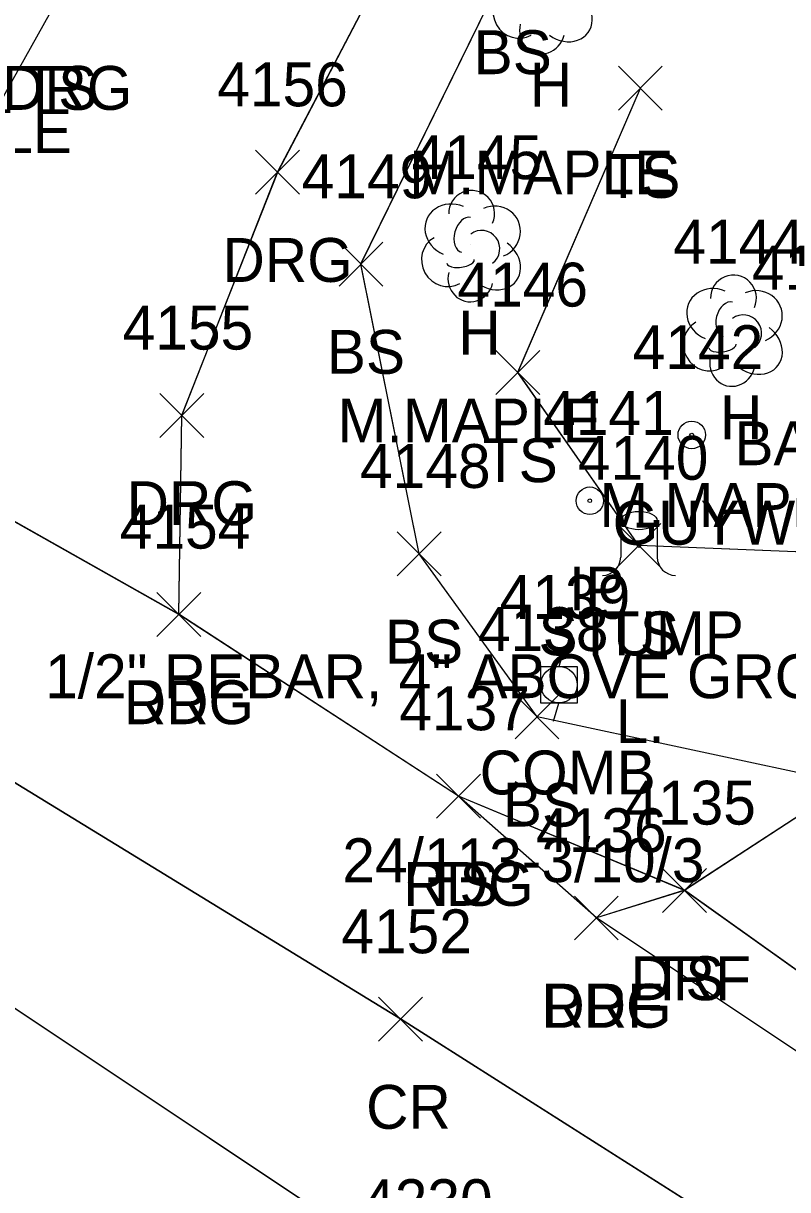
# Model space of a CAD drawing. Extents: x 1554668 to 1563881, y 831386 to 834374.
# Drawn here: x 1562024.3 to 1562059.1, y 834220.5 to 834273.7 of the extents above; entities that cross this region are included whole.
import ezdxf

# ---------------------------------------------------------------- set-up
doc = ezdxf.new("R2010")
doc.units = 0
for name, color, linetype in [('L_A', 7, 'Continuous'), ('L_C', 7, 'Continuous'), ('L_I', 7, 'Continuous'), ('L_TIC', 7, 'Continuous'), ('LELB', 7, 'Continuous'), ('LTD', 7, 'Continuous'), ('LTS', 7, 'Continuous'), ('M_A', 7, 'Continuous'), ('M_C', 7, 'Continuous'), ('M_I', 7, 'Continuous'), ('MPIR', 7, 'Continuous'), ('P_A', 7, 'Continuous'), ('P_I', 7, 'Continuous'), ('P_TIC', 7, 'Continuous'), ('PEU', 7, 'Continuous'), ('PRC', 7, 'Continuous'), ('R_A', 7, 'Continuous'), ('R_I', 7, 'Continuous'), ('R_TIC', 7, 'Continuous'), ('RDF', 7, 'Continuous'), ('RDG', 7, 'Continuous'), ('U_A', 7, 'Continuous'), ('U_C', 7, 'Continuous'), ('U_I', 7, 'Continuous'), ('UP', 7, 'Continuous'), ('UPGW', 7, 'Continuous')]:
    doc.layers.add(name, color=color, linetype=linetype)

msp = doc.modelspace()

# ---------------------------------------------------------------- linework, layer by layer
at = {"layer": 'L_TIC'}
for points in [[(1562051.426, 834269.699), (1562053.426, 834271.699)], [(1562053.426, 834269.699), (1562051.426, 834271.699)], [(1562038.694, 834261.682), (1562040.694, 834263.682)], [(1562040.694, 834261.682), (1562038.694, 834263.682)], [(1562045.838, 834256.746), (1562047.838, 834258.746)], [(1562047.838, 834256.746), (1562045.838, 834258.746)], [(1562051.36, 834248.855), (1562053.36, 834250.855)], [(1562053.36, 834248.855), (1562051.36, 834250.855)], [(1562041.344, 834248.48), (1562043.344, 834250.48)], [(1562043.344, 834248.48), (1562041.344, 834250.48)], [(1562046.718, 834241.051), (1562048.718, 834243.051)], [(1562048.718, 834241.051), (1562046.718, 834243.051)], [(1562043.136, 834237.439), (1562045.136, 834239.439)], [(1562045.136, 834237.439), (1562043.136, 834239.439)], [(1562053.435, 834233.14), (1562055.435, 834235.14)], [(1562055.435, 834233.14), (1562053.435, 834235.14)]]:
    msp.add_lwpolyline(points, dxfattribs=at)
at = {"layer": 'LELB'}
for points in [[(1562274.311, 834171.295), (1562269.484, 834154.313), (1562262.795, 834141.276), (1562258.276, 834136.975), (1562255.128, 834134.812), (1562254.728, 834133.197), (1562248.809, 834134.873), (1562237.208, 834134.057), (1562209.954, 834148.175), (1562185.935, 834159.727), (1562146.304, 834177.205), (1562126.106, 834188.395), (1562101.793, 834201.545), (1562083.048, 834212.879), (1562078.957, 834226.941), (1562061.906, 834239.007), (1562047.718, 834242.051), (1562042.344, 834249.48), (1562039.694, 834262.682), (1562046.385, 834276.336)], [(1562274.319, 834171.3), (1562269.492, 834154.32), (1562262.801, 834141.275), (1562258.282, 834136.979), (1562255.131, 834134.817), (1562254.731, 834133.201), (1562248.817, 834134.876), (1562237.219, 834134.061), (1562209.965, 834148.177), (1562185.942, 834159.73), (1562146.305, 834177.208), (1562126.107, 834188.395), (1562101.796, 834201.554), (1562083.051, 834212.885), (1562078.962, 834226.944), (1562061.908, 834239.014), (1562047.722, 834242.055), (1562042.349, 834249.484), (1562039.695, 834262.69), (1562046.39, 834276.339)], [(1562274.319, 834171.3), (1562269.492, 834154.32), (1562262.801, 834141.275), (1562258.282, 834136.979), (1562255.131, 834134.817), (1562254.731, 834133.201), (1562248.817, 834134.876), (1562237.219, 834134.061), (1562209.965, 834148.177), (1562185.942, 834159.73), (1562146.305, 834177.208), (1562126.107, 834188.395), (1562101.796, 834201.554), (1562083.051, 834212.885), (1562078.962, 834226.944), (1562061.908, 834239.014), (1562047.722, 834242.055), (1562042.349, 834249.484), (1562039.695, 834262.69), (1562046.39, 834276.339)], [(1562274.319, 834171.3), (1562269.492, 834154.32), (1562262.801, 834141.275), (1562258.282, 834136.979), (1562255.131, 834134.817), (1562254.731, 834133.201), (1562248.817, 834134.876), (1562237.219, 834134.061), (1562209.965, 834148.177), (1562185.942, 834159.73), (1562146.305, 834177.208), (1562126.107, 834188.395), (1562101.796, 834201.554), (1562083.051, 834212.885), (1562078.962, 834226.944), (1562061.908, 834239.014), (1562047.722, 834242.055), (1562042.349, 834249.484), (1562039.695, 834262.69), (1562046.39, 834276.339)], [(1562260.28, 834152.616), (1562249.48, 834140.941), (1562236.559, 834142.263), (1562217.637, 834150.933), (1562211.156, 834152.868), (1562187.668, 834163.839), (1562148.783, 834181.373), (1562128.183, 834192.376), (1562104.921, 834206.075), (1562084.843, 834218.482), (1562091.073, 834236.987), (1562082.29, 834244.955), (1562070.789, 834249.121), (1562052.36, 834249.855), (1562046.838, 834257.746), (1562052.426, 834270.699)], [(1562260.287, 834152.618), (1562249.484, 834140.947), (1562236.562, 834142.268), (1562217.643, 834150.937), (1562211.165, 834152.871), (1562187.679, 834163.841), (1562148.788, 834181.377), (1562128.187, 834192.38), (1562104.925, 834206.082), (1562084.849, 834218.484), (1562091.079, 834236.988), (1562082.294, 834244.96), (1562070.796, 834249.121), (1562052.362, 834249.861), (1562046.841, 834257.752), (1562052.431, 834270.702)], [(1562260.287, 834152.618), (1562249.484, 834140.947), (1562236.562, 834142.268), (1562217.643, 834150.937), (1562211.165, 834152.871), (1562187.679, 834163.841), (1562148.788, 834181.377), (1562128.187, 834192.38), (1562104.925, 834206.082), (1562084.849, 834218.484), (1562091.079, 834236.988), (1562082.294, 834244.96), (1562070.796, 834249.121), (1562052.362, 834249.861), (1562046.841, 834257.752), (1562052.431, 834270.702)], [(1562260.287, 834152.618), (1562249.484, 834140.947), (1562236.562, 834142.268), (1562217.643, 834150.937), (1562211.165, 834152.871), (1562187.679, 834163.841), (1562148.788, 834181.377), (1562128.187, 834192.38), (1562104.925, 834206.082), (1562084.849, 834218.484), (1562091.079, 834236.988), (1562082.294, 834244.96), (1562070.796, 834249.121), (1562052.362, 834249.861), (1562046.841, 834257.752), (1562052.431, 834270.702)], [(1562082.336, 834212.024), (1562077.402, 834217.776), (1562054.435, 834234.14), (1562044.136, 834238.439)], [(1562082.34, 834212.029), (1562077.406, 834217.78), (1562054.437, 834234.148), (1562044.143, 834238.441)], [(1562082.34, 834212.029), (1562077.406, 834217.78), (1562054.437, 834234.148), (1562044.143, 834238.441)], [(1562082.34, 834212.029), (1562077.406, 834217.78), (1562054.437, 834234.148), (1562044.143, 834238.441)]]:
    msp.add_lwpolyline(points, dxfattribs=at)
at = {"layer": 'LTD'}
for p, q in [((1562044.694, 834263.553), (1562044.694, 834263.553)), ((1562044.694, 834263.553), (1562044.694, 834263.553)), ((1562056.624, 834259.703), (1562056.624, 834259.703)), ((1562056.624, 834259.703), (1562056.624, 834259.703))]:
    msp.add_line(p, q, dxfattribs=at)
for centre in [(1562044.74, 834264.987), (1562056.67, 834261.136)]:
    msp.add_arc(centre, 1.047, 335.5272, 180.9563, dxfattribs=at)
for centre, major_axis, ratio, start_param, end_param in [((1562046.871, 834274.149), (0.584, -1.042), 0.959034, 3.141593, 6.283185), ((1562048.954, 834274.025), (-1.09, 0.792), 0.841452, 1.570796, 4.712389), ((1562047.954, 834273.358), (0.265, 1.061), 0.942809, 1.570796, 4.712389), ((1562043.902, 834264.219), (1.21, -0.512), 0.895232, 1.570796, 4.712389), ((1562045.735, 834264.136), (-1.141, -0.483), 0.949671, 1.570796, 4.712389), ((1562044.485, 834264.011), (-0.208, -0.792), 0.645439, 3.141593, 6.283185), ((1562043.61, 834262.844), (0.584, -1.042), 0.959034, 3.141593, 6.283185), ((1562045.194, 834263.386), (-0.5, 0.667), 0.989748, 3.141593, 6.283185), ((1562045.694, 834262.72), (-1.09, 0.792), 0.841452, 1.570796, 4.712389), ((1562044.235, 834262.803), (-0.625, -0.083), 0.423636, 0, 3.141593), ((1562044.694, 834262.053), (0.265, 1.061), 0.942809, 1.570796, 4.712389), ((1562055.832, 834260.369), (1.21, -0.512), 0.895232, 1.570796, 4.712389), ((1562057.665, 834260.286), (-1.141, -0.483), 0.949671, 1.570796, 4.712389), ((1562056.415, 834260.161), (-0.208, -0.792), 0.645439, 3.141593, 6.283185), ((1562057.124, 834259.536), (-0.5, 0.667), 0.989748, 3.141593, 6.283185), ((1562055.541, 834258.994), (0.584, -1.042), 0.959034, 3.141593, 6.283185), ((1562057.624, 834258.869), (-1.09, 0.792), 0.841452, 1.570796, 4.712389), ((1562056.166, 834258.952), (-0.625, -0.083), 0.423636, 0, 3.141593), ((1562056.624, 834258.203), (0.265, 1.061), 0.942809, 1.570796, 4.712389)]:
    msp.add_ellipse(centre, major_axis=major_axis, ratio=ratio, start_param=start_param, end_param=end_param, dxfattribs=at)
at = {"layer": 'LTS'}
for p, q in [((1562051.531, 834250.995), (1562051.531, 834249.328)), ((1562053.197, 834250.828), (1562053.197, 834250.995)), ((1562053.197, 834250.995), (1562053.197, 834249.328)), ((1562052.364, 834249.853), (1562052.364, 834249.853)), ((1562052.364, 834249.853), (1562052.364, 834249.853)), ((1562052.364, 834249.828), (1562052.364, 834249.828))]:
    msp.add_line(p, q, dxfattribs=at)
msp.add_circle((1562052.364, 834249.853), 0.0833, dxfattribs=at)
for centre, start, end in [((1562050.697, 834249.328), 270, 360), ((1562054.031, 834249.328), 180, 270)]:
    msp.add_arc(centre, 0.833, start, end, dxfattribs=at)
msp.add_ellipse((1562052.364, 834250.995), major_axis=(-0.833, 0), ratio=0.5, dxfattribs=at)
at = {"layer": 'MPIR'}
for radius in [0.625, 0.0833]:
    msp.add_circle((1562050.124, 834251.9), radius, dxfattribs=at)
at = {"layer": 'P_TIC'}
for points in [[(1562030.394, 834245.717), (1562032.394, 834247.717)], [(1562032.394, 834245.717), (1562030.394, 834247.717)], [(1562043.136, 834237.439), (1562045.136, 834239.439)], [(1562045.136, 834237.439), (1562043.136, 834239.439)], [(1562049.423, 834231.886), (1562051.423, 834233.886)], [(1562051.423, 834231.886), (1562049.423, 834233.886)], [(1562040.495, 834227.278), (1562042.495, 834229.278)], [(1562042.495, 834227.278), (1562040.495, 834229.278)]]:
    msp.add_lwpolyline(points, dxfattribs=at)
at = {"layer": 'PEU'}
for points in [[(1562100.961, 834200.301), (1562082.336, 834212.024), (1562078.17, 834214.391), (1562050.423, 834232.886), (1562044.136, 834238.439), (1562031.394, 834246.717), (1562008.824, 834259.447), (1561980.823, 834275.017), (1561963.212, 834287.936), (1561950.466, 834298.855), (1561935.06, 834310.381), (1561902.996, 834336.224), (1561874.594, 834353.486)], [(1562100.966, 834200.302), (1562082.34, 834212.029), (1562078.172, 834214.399), (1562050.425, 834232.893), (1562044.143, 834238.441), (1562031.395, 834246.724), (1562008.826, 834259.454), (1561980.829, 834275.018), (1561963.222, 834287.936), (1561950.472, 834298.857), (1561935.067, 834310.383), (1561903, 834336.227), (1561874.6, 834353.489)], [(1562100.966, 834200.302), (1562082.34, 834212.029), (1562078.172, 834214.399), (1562050.425, 834232.893), (1562044.143, 834238.441), (1562031.395, 834246.724), (1562008.826, 834259.454), (1561980.829, 834275.018), (1561963.222, 834287.936), (1561950.472, 834298.857), (1561935.067, 834310.383), (1561903, 834336.227), (1561874.6, 834353.489)], [(1562100.966, 834200.302), (1562082.34, 834212.029), (1562078.172, 834214.399), (1562050.425, 834232.893), (1562044.143, 834238.441), (1562031.395, 834246.724), (1562008.826, 834259.454), (1561980.829, 834275.018), (1561963.222, 834287.936), (1561950.472, 834298.857), (1561935.067, 834310.383), (1561903, 834336.227), (1561874.6, 834353.489)], [(1561938.492, 834286.804), (1561967.469, 834265.707), (1561993.867, 834247.497), (1562001.767, 834243.533), (1562043.094, 834215.981), (1562070.402, 834197.447), (1562101.047, 834180.134), (1562110.546, 834175.405), (1562151.878, 834156.065), (1562177.496, 834144.272), (1562206.565, 834132.055), (1562231.908, 834122.571), (1562256.629, 834113.703), (1562290.496, 834101.553), (1562318.446, 834090.049), (1562334.906, 834086.266), (1562364.5, 834080.766), (1562384.303, 834077.346), (1562395.73, 834075.709), (1562408.433, 834072.338), (1562435.459, 834067.179)], [(1561938.503, 834286.804), (1561967.476, 834265.709), (1561993.875, 834247.495), (1562001.774, 834243.534), (1562043.103, 834215.981), (1562070.407, 834197.45), (1562101.053, 834180.137), (1562110.549, 834175.411), (1562151.879, 834156.07), (1562177.498, 834144.277), (1562206.569, 834132.059), (1562231.918, 834122.576), (1562256.636, 834113.711), (1562290.5, 834101.559), (1562318.455, 834090.052), (1562334.912, 834086.27), (1562364.51, 834080.769), (1562384.309, 834077.35), (1562395.737, 834075.714), (1562408.442, 834072.346), (1562435.465, 834067.183)], [(1561938.503, 834286.804), (1561967.476, 834265.709), (1561993.875, 834247.495), (1562001.774, 834243.534), (1562043.103, 834215.981), (1562070.407, 834197.45), (1562101.053, 834180.137), (1562110.549, 834175.411), (1562151.879, 834156.07), (1562177.498, 834144.277), (1562206.569, 834132.059), (1562231.918, 834122.576), (1562256.636, 834113.711), (1562290.5, 834101.559), (1562318.455, 834090.052), (1562334.912, 834086.27), (1562364.51, 834080.769), (1562384.309, 834077.35), (1562395.737, 834075.714), (1562408.442, 834072.346), (1562435.465, 834067.183)], [(1561938.503, 834286.804), (1561967.476, 834265.709), (1561993.875, 834247.495), (1562001.774, 834243.534), (1562043.103, 834215.981), (1562070.407, 834197.45), (1562101.053, 834180.137), (1562110.549, 834175.411), (1562151.879, 834156.07), (1562177.498, 834144.277), (1562206.569, 834132.059), (1562231.918, 834122.576), (1562256.636, 834113.711), (1562290.5, 834101.559), (1562318.455, 834090.052), (1562334.912, 834086.27), (1562364.51, 834080.769), (1562384.309, 834077.35), (1562395.737, 834075.714), (1562408.442, 834072.346), (1562435.465, 834067.183)]]:
    msp.add_lwpolyline(points, dxfattribs=at)
at = {"layer": 'PRC'}
for points in [[(1562507.663, 834058.473), (1562489.819, 834063.697), (1562466.193, 834069.126), (1562436.129, 834075.748), (1562408.218, 834079.724), (1562320.462, 834097.246), (1562291.247, 834107.325), (1562261.719, 834117.67), (1562206.924, 834138.361), (1562180.714, 834150.238), (1562141.773, 834168.724), (1562097.331, 834192.804), (1562041.495, 834228.278), (1562010.592, 834247.192), (1561969.731, 834271.926), (1561947.65, 834288.488), (1561929.769, 834303.06), (1561897.798, 834328.164), (1561868.944, 834345.787)], [(1562507.673, 834058.475), (1562489.821, 834063.703), (1562466.195, 834069.132), (1562436.136, 834075.752), (1562408.228, 834079.731), (1562320.469, 834097.25), (1562291.251, 834107.331), (1562261.726, 834117.669), (1562206.928, 834138.365), (1562180.725, 834150.241), (1562141.776, 834168.728), (1562097.334, 834192.81), (1562041.498, 834228.283), (1562010.595, 834247.198), (1561969.736, 834271.928), (1561947.66, 834288.488), (1561929.776, 834303.061), (1561897.805, 834328.165), (1561868.953, 834345.787)], [(1562507.673, 834058.475), (1562489.821, 834063.703), (1562466.195, 834069.132), (1562436.136, 834075.752), (1562408.228, 834079.731), (1562320.469, 834097.25), (1562291.251, 834107.331), (1562261.726, 834117.669), (1562206.928, 834138.365), (1562180.725, 834150.241), (1562141.776, 834168.728), (1562097.334, 834192.81), (1562041.498, 834228.283), (1562010.595, 834247.198), (1561969.736, 834271.928), (1561947.66, 834288.488), (1561929.776, 834303.061), (1561897.805, 834328.165), (1561868.953, 834345.787)], [(1562507.673, 834058.475), (1562489.821, 834063.703), (1562466.195, 834069.132), (1562436.136, 834075.752), (1562408.228, 834079.731), (1562320.469, 834097.25), (1562291.251, 834107.331), (1562261.726, 834117.669), (1562206.928, 834138.365), (1562180.725, 834150.241), (1562141.776, 834168.728), (1562097.334, 834192.81), (1562041.498, 834228.283), (1562010.595, 834247.198), (1561969.736, 834271.928), (1561947.66, 834288.488), (1561929.776, 834303.061), (1561897.805, 834328.165), (1561868.953, 834345.787)]]:
    msp.add_lwpolyline(points, dxfattribs=at)
at = {"layer": 'R_TIC'}
for points in [[(1562034.892, 834265.87), (1562036.892, 834267.87)], [(1562036.892, 834265.87), (1562034.892, 834267.87)], [(1562030.525, 834254.786), (1562032.525, 834256.786)], [(1562032.525, 834254.786), (1562030.525, 834256.786)], [(1562030.394, 834245.717), (1562032.394, 834247.717)], [(1562032.394, 834245.717), (1562030.394, 834247.717)], [(1562053.435, 834233.14), (1562055.435, 834235.14)], [(1562055.435, 834233.14), (1562053.435, 834235.14)], [(1562049.423, 834231.886), (1562051.423, 834233.886)], [(1562051.423, 834231.886), (1562049.423, 834233.886)]]:
    msp.add_lwpolyline(points, dxfattribs=at)
at = {"layer": 'RDF'}
for points in [[(1562073.098, 834252.843), (1562070.789, 834249.121), (1562061.906, 834239.007), (1562054.435, 834234.14), (1562050.423, 834232.886)], [(1562073.1, 834252.852), (1562070.796, 834249.121), (1562061.908, 834239.014), (1562054.437, 834234.148), (1562050.425, 834232.893)], [(1562073.1, 834252.852), (1562070.796, 834249.121), (1562061.908, 834239.014), (1562054.437, 834234.148), (1562050.425, 834232.893)], [(1562073.1, 834252.852), (1562070.796, 834249.121), (1562061.908, 834239.014), (1562054.437, 834234.148), (1562050.425, 834232.893)]]:
    msp.add_lwpolyline(points, dxfattribs=at)
at = {"layer": 'RDG'}
for points in [[(1562035.212, 834293.596), (1562025.85, 834274.71), (1562021.06, 834266.167), (1562008.824, 834259.447)], [(1562035.214, 834293.604), (1562025.852, 834274.717), (1562021.062, 834266.172), (1562008.826, 834259.454)], [(1562035.214, 834293.604), (1562025.852, 834274.717), (1562021.062, 834266.172), (1562008.826, 834259.454)], [(1562035.214, 834293.604), (1562025.852, 834274.717), (1562021.062, 834266.172), (1562008.826, 834259.454)], [(1562031.394, 834246.717), (1562031.525, 834255.786), (1562035.892, 834266.87), (1562043.437, 834281.288)], [(1562031.395, 834246.724), (1562031.527, 834255.792), (1562035.898, 834266.872), (1562043.442, 834281.291)], [(1562031.395, 834246.724), (1562031.527, 834255.792), (1562035.898, 834266.872), (1562043.442, 834281.291)], [(1562031.395, 834246.724), (1562031.527, 834255.792), (1562035.898, 834266.872), (1562043.442, 834281.291)]]:
    msp.add_lwpolyline(points, dxfattribs=at)
at = {"layer": 'UP'}
for p, q in [((1562048.968, 834245.182), (1562048.718, 834244.349)), ((1562047.885, 834242.682), (1562047.885, 834244.349)), ((1562047.885, 834244.349), (1562049.552, 834244.349)), ((1562049.552, 834244.349), (1562049.552, 834242.682)), ((1562048.718, 834243.516), (1562048.718, 834243.516)), ((1562049.552, 834242.682), (1562047.885, 834242.682)), ((1562048.468, 834241.849), (1562048.718, 834242.682))]:
    msp.add_line(p, q, dxfattribs=at)
msp.add_circle((1562048.718, 834243.516), 0.833, dxfattribs=at)
at = {"layer": 'UPGW'}
for radius in [0.625, 0.0833]:
    msp.add_circle((1562054.769, 834254.896), radius, dxfattribs=at)

# ---------------------------------------------------------------- texts
at = {"layer": 'L_A'}
for s, p in [('BS', (1562044.826, 834271.336)), ('H', (1562047.387, 834269.858)), ('TS', (1562024.26, 834269.71)), ('TS', (1562050.835, 834265.699)), ('H', (1562044.127, 834258.553)), ('BS', (1562038.135, 834257.682)), ('H', (1562056.057, 834254.703)), ('BARN', (1562056.712, 834253.516)), ('TS', (1562045.247, 834252.746)), ('STUMP', (1562047.785, 834244.855)), ('TS', (1562050.769, 834244.855)), ('BS', (1562040.785, 834244.48)), ('BS', (1562046.159, 834237.051)), ('TS', (1562042.546, 834233.439)), ('TS', (1562052.845, 834229.14))]:
    msp.add_text(s, height=2, dxfattribs=at).set_placement(p)
at = {"layer": 'L_C'}
for s, p in [('M.MAPLE', (1562014.483, 834267.741)), ('M.MAPLE', (1562041.891, 834265.858)), ('M.MAPLE', (1562038.631, 834254.553)), ('M.MAPLE', (1562050.561, 834250.703)), ('L.', (1562051.304, 834240.855))]:
    msp.add_text(s, height=2, dxfattribs=at).set_placement(p)
at = {"layer": 'L_I'}
for s, p in [('4145', (1562042.001, 834266.553)), ('4149', (1562036.993, 834265.682)), ('4144', (1562053.931, 834262.703)), ('4143', (1562057.508, 834261.516)), ('4146', (1562044.09, 834260.746)), ('4140', (1562049.58, 834252.855)), ('4140', (1562049.58, 834252.855)), ('4148', (1562039.651, 834252.48)), ('4138', (1562045.025, 834245.051)), ('4137', (1562041.443, 834241.439)), ('4135', (1562051.742, 834237.14))]:
    msp.add_text(s, height=2, dxfattribs=at).set_placement(p)
at = {"layer": 'M_A'}
msp.add_text('IP', height=2, dxfattribs=at).set_placement((1562049.172, 834246.9))
at = {"layer": 'M_C'}
msp.add_text('1/2" REBAR, 4" ABOVE GROUND, W/', height=2, dxfattribs=at).set_placement((1562025.298, 834242.9))
at = {"layer": 'M_I'}
msp.add_text('4141', height=2, dxfattribs=at).set_placement((1562047.998, 834254.9))
at = {"layer": 'P_A'}
for s, p in [('RDG', (1562028.882, 834241.717)), ('RDG', (1562041.624, 834233.439)), ('RDG', (1562047.911, 834227.886)), ('CR', (1562039.928, 834223.278))]:
    msp.add_text(s, height=2, dxfattribs=at).set_placement(p)
at = {"layer": 'P_I'}
for s, p in [('4154', (1562028.701, 834249.717)), ('4137', (1562041.443, 834241.439)), ('4136', (1562047.675, 834235.886)), ('4152', (1562038.802, 834231.278)), ('4230', (1562039.747, 834218.981))]:
    msp.add_text(s, height=2, dxfattribs=at).set_placement(p)
at = {"layer": 'R_A'}
for s, p in [('DRG', (1562023.338, 834269.71)), ('DRG', (1562033.38, 834261.87)), ('DRG', (1562029.013, 834250.786)), ('DRG', (1562028.882, 834241.717)), ('DRF', (1562051.971, 834229.14)), ('DRF', (1562047.959, 834227.886))]:
    msp.add_text(s, height=2, dxfattribs=at).set_placement(p)
at = {"layer": 'R_I'}
for s, p in [('4156', (1562033.144, 834269.87)), ('4155', (1562028.832, 834258.786)), ('4154', (1562028.701, 834249.717)), ('4135', (1562051.742, 834237.14)), ('4136', (1562047.675, 834235.886)), ('4230', (1562039.747, 834218.981))]:
    msp.add_text(s, height=2, dxfattribs=at).set_placement(p)
at = {"layer": 'U_A'}
for s, p in [('GUYW', (1562051.163, 834249.896)), ('COMB', (1562045.104, 834238.516))]:
    msp.add_text(s, height=2, dxfattribs=at).set_placement(p)
at = {"layer": 'U_C'}
msp.add_text('24/113-3/10/3', height=2, dxfattribs=at).set_placement((1562038.844, 834234.516))
at = {"layer": 'U_I'}
for s, p in [('4142', (1562052.076, 834257.896)), ('4139', (1562046.018, 834246.516))]:
    msp.add_text(s, height=2, dxfattribs=at).set_placement(p)

doc.saveas('drawing.dxf')
